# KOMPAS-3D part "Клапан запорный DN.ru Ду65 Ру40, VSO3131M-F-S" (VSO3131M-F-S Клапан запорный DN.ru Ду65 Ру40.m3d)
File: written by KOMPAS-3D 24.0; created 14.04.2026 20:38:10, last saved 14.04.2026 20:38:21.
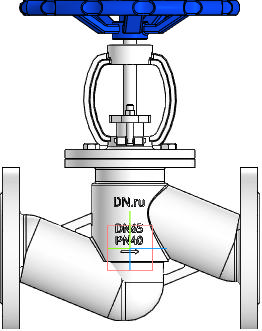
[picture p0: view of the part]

Document properties: Автор: R2D2; Полное имя файла: E:\Работа\Зайцев\VSO3131M-F-S Клапан запорный DN.ru Ду15-100 Ру40\DN65\VSO3131M-F-S Клапан запорный DN.ru Ду65 Ру40.m3d

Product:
- Part/product: Клапан запорный DN.ru Ду65 Ру40  | designation VSO3131M-F-S
    Масса: 17.64
    Раздел спецификации: Прочие изделия
    Примечание: D090-02143

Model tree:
1. Операция без истории:2

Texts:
  VSO3131M-F-S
